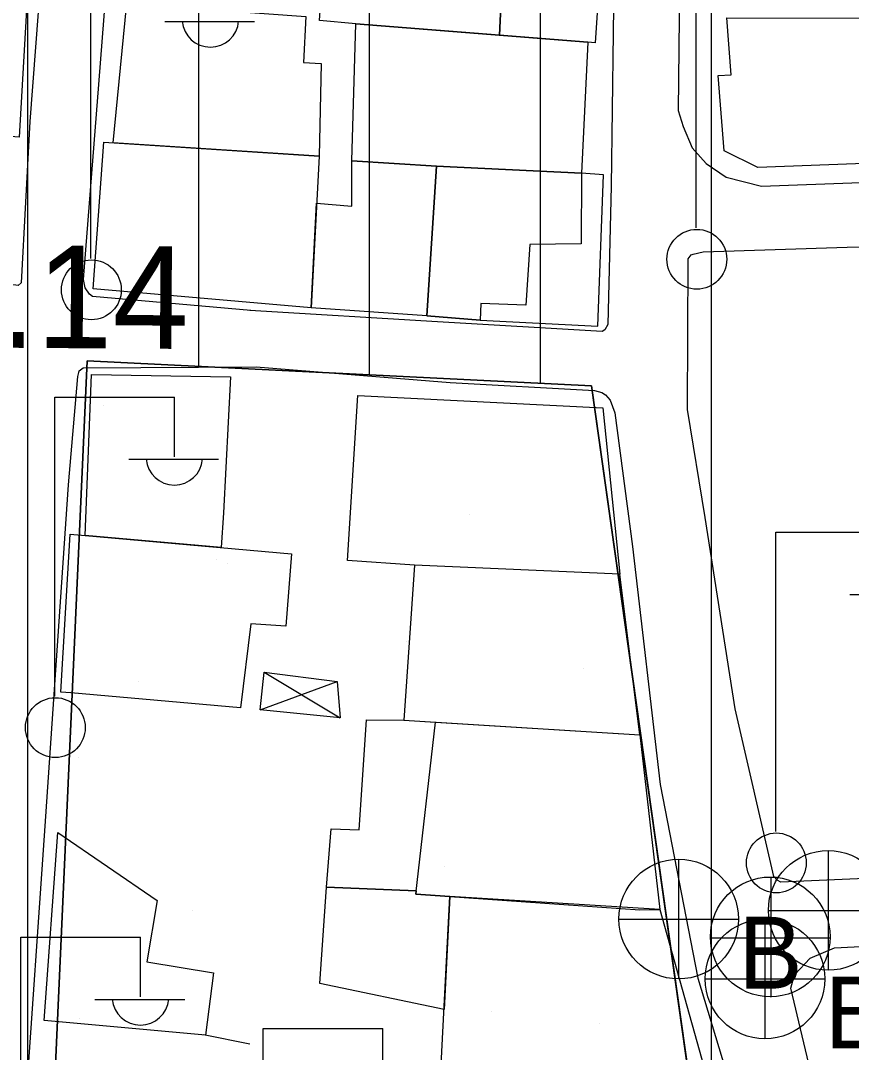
# Model space of a CAD drawing. Extents: x 417997 to 421451, y 4451742 to 4455216.
# Drawn here: x 419705.5 to 419754.1, y 4452544.2 to 4452604.6 of the extents above; entities that cross this region are included whole.
import ezdxf

# ---------------------------------------------------------------- set-up
doc = ezdxf.new("R2010")
doc.units = 0
for name, color, linetype in [('ADA', 7, 'Continuous'), ('B_Mesken', 7, 'Continuous'), ('B_Sundurma', 7, 'Continuous'), ('B_Teras', 7, 'Continuous'), ('Default', 7, 'Continuous'), ('PL_AYA_PARK_DINLENME', 7, 'Continuous'), ('PL_KON_MEV_350', 7, 'Continuous'), ('S_Elektrik_Diregi', 7, 'Continuous'), ('S_Rogar_Kapagi', 7, 'Continuous'), ('S_Rogar_Kapagi_Buski', 7, 'Continuous'), ('Sinir_Duvar_tek_tarafa_ait', 7, 'Continuous'), ('TR_ORTAYOGUNKONUT', 7, 'Continuous'), ('TR_PARKALANI', 7, 'Continuous'), ('Y_Yol_Kotu', 7, 'Continuous'), ('Yol_Sose', 7, 'Continuous')]:
    doc.layers.add(name, color=color, linetype=linetype)

# ---------------------------------------------------------------- blocks, each defined once
blk = doc.blocks.new('POINT_DISPLAY')
at = {"layer": 'Default'}
blk.add_line((0, 0), (0, 0), dxfattribs=at)

msp = doc.modelspace()

# ---------------------------------------------------------------- linework, layer by layer
at = {"layer": 'ADA'}
for p, q in [((419707.455, 4452540.909), (419709.422, 4452584.671)), ((419707.455, 4452540.909), (419709.422, 4452584.671)), ((419709.422, 4452584.671), (419738.924, 4452583.196)), ((419709.422, 4452584.671), (419738.924, 4452583.196)), ((419738.924, 4452583.196), (419744.825, 4452541.401)), ((419738.924, 4452583.196), (419744.825, 4452541.401))]:
    msp.add_line(p, q, dxfattribs=at)
at = {"layer": 'B_Mesken'}
for points in [[(419725.136, 4452604.384), (419723.02, 4452604.57), (419723.711, 4452614.614), (419729.791, 4452613.902), (419733.998, 4452613.408), (419733.54, 4452603.719)], [(419733.54, 4452603.719), (419733.998, 4452613.408), (419738.936, 4452613.018), (419739.793, 4452612.964), (419739.15, 4452603.264), (419738.71, 4452603.311)], [(419755.808, 4452613.02), (419762.653, 4452613.18), (419764.246, 4452596.565), (419748.658, 4452595.965), (419746.701, 4452596.949), (419746.336, 4452601.351), (419747.097, 4452601.395), (419746.849, 4452604.727), (419755.984, 4452604.701)], [(419691.408, 4452598.864), (419691.916, 4452607.049), (419705.904, 4452605.887), (419705.445, 4452597.747)], [(419710.938, 4452597.42), (419711.726, 4452605.396), (419715.187, 4452605.307), (419722.209, 4452604.812), (419722.08, 4452602.108), (419723.121, 4452602.056), (419722.993, 4452596.633)], [(419729.864, 4452596.047), (419724.919, 4452596.356), (419725.136, 4452604.384), (419738.71, 4452603.311), (419738.352, 4452595.65)], [(419709.77, 4452588.87), (419710.401, 4452597.455), (419722.993, 4452596.633), (419722.531, 4452587.768)], [(419729.294, 4452587.299), (419722.531, 4452587.768), (419722.85, 4452593.888), (419724.918, 4452593.721), (419724.919, 4452596.356), (419729.864, 4452596.047)], [(419732.417, 4452587.046), (419739.305, 4452586.691), (419739.636, 4452595.544), (419738.352, 4452595.65), (419729.864, 4452596.047), (419729.294, 4452587.299)], [(419717.404, 4452575.786), (419717.257, 4452573.75), (419709.305, 4452574.453), (419709.676, 4452583.866), (419717.808, 4452583.737)], [(419725.254, 4452582.646), (419739.591, 4452581.914), (419740.584, 4452572.182), (419728.572, 4452572.725), (419724.657, 4452572.985)], [(419708.468, 4452565.241), (419707.881, 4452565.283), (419708.424, 4452574.531), (419721.382, 4452573.385), (419721.055, 4452569.141), (419718.996, 4452569.288), (419718.394, 4452564.379)], [(419728.572, 4452572.725), (419727.956, 4452563.649), (419741.769, 4452562.795), (419740.584, 4452572.182)], [(419728.682, 4452553.676), (419723.432, 4452553.884), (419723.705, 4452557.286), (419725.341, 4452557.237), (419725.759, 4452563.675), (419727.956, 4452563.649), (419729.797, 4452563.535), (419741.769, 4452562.795), (419742.93, 4452552.576), (419730.642, 4452553.345), (419728.66, 4452553.483)], [(419730.303, 4452546.725), (419723.039, 4452548.243), (419723.432, 4452553.884), (419728.682, 4452553.676), (419728.66, 4452553.483), (419730.642, 4452553.345)], [(419741.768, 4452552.558), (419742.93, 4452552.576), (419747.406, 4452536.654), (419730.1, 4452542.755), (419730.642, 4452553.345)]]:
    msp.add_lwpolyline(points, close=True, dxfattribs=at)
at = {"layer": 'B_Sundurma'}
for p, q in [((419719.785, 4452566.456), (419724.228, 4452563.786)), ((419719.555, 4452564.261), (419724.06, 4452565.909))]:
    msp.add_line(p, q, dxfattribs=at)
msp.add_lwpolyline([(419719.555, 4452564.261), (419719.785, 4452566.456), (419724.06, 4452565.909), (419724.228, 4452563.786)], close=True, dxfattribs=at)
at = {"layer": 'B_Teras'}
for points in [[(419729.294, 4452587.299), (419729.864, 4452596.047), (419738.352, 4452595.65), (419738.33, 4452591.504), (419735.317, 4452591.465), (419735.091, 4452587.921), (419732.466, 4452588.029), (419732.417, 4452587.046)], [(419741.769, 4452562.795), (419742.93, 4452552.576), (419730.642, 4452553.345), (419728.66, 4452553.483), (419729.797, 4452563.535)], [(419706.905, 4452546.091), (419707.717, 4452557.085), (419713.521, 4452553.105), (419712.907, 4452549.513), (419716.825, 4452548.876), (419716.345, 4452545.231)]]:
    msp.add_lwpolyline(points, close=True, dxfattribs=at)
at = {"layer": 'PL_AYA_PARK_DINLENME'}
msp.add_lwpolyline([(419738.924, 4452583.196), (419744.825, 4452541.401), (419707.455, 4452540.909), (419709.422, 4452584.671)], close=True, dxfattribs=at)
msp.add_lwpolyline([(419738.924, 4452583.196), (419744.825, 4452541.401), (419707.455, 4452540.909), (419709.422, 4452584.671)], close=True, dxfattribs=at)
at = {"layer": 'PL_KON_MEV_350'}
msp.add_lwpolyline([(419816.019, 4452500.983), (419737, 4452491.84), (419733.027, 4452491.433), (419729.045, 4452491.133), (419725.057, 4452490.939), (419721.064, 4452490.851), (419717.071, 4452490.869), (419713.08, 4452490.994), (419709.093, 4452491.225), (419705.114, 4452491.562), (419667.93, 4452495.209), (419665.168, 4452517.307), (419707.455, 4452540.909), (419744.825, 4452541.401), (419738.924, 4452583.196), (419709.422, 4452584.671), (419707.455, 4452540.909), (419665.168, 4452517.307), (419625.831, 4452515.34), (419623.77, 4452499.541), (419582.687, 4452503.571)], dxfattribs=at)
at = {"layer": 'S_Elektrik_Diregi'}
for p, q in [((419745.06, 4452592.442), (419745.06, 4452609.942)), ((419709.634, 4452590.657), (419709.634, 4452608.157)), ((419713.974, 4452604.517), (419719.224, 4452604.517)), ((419707.525, 4452565.049), (419707.525, 4452582.549)), ((419707.525, 4452582.549), (419714.525, 4452582.549)), ((419714.525, 4452579.049), (419714.525, 4452582.549)), ((419711.865, 4452578.909), (419717.115, 4452578.909)), ((419749.711, 4452557.138), (419749.711, 4452574.638)), ((419749.711, 4452574.638), (419756.711, 4452574.638)), ((419754.051, 4452570.998), (419759.301, 4452570.998)), ((419705.541, 4452533.46), (419705.541, 4452550.96)), ((419705.541, 4452550.96), (419712.541, 4452550.96)), ((419712.541, 4452547.46), (419712.541, 4452550.96)), ((419709.881, 4452547.32), (419715.131, 4452547.32)), ((419719.718, 4452528.113), (419719.717, 4452545.613)), ((419719.717, 4452545.613), (419726.718, 4452545.613)), ((419726.718, 4452542.113), (419726.718, 4452545.613))]:
    msp.add_line(p, q, dxfattribs=at)
for centre in [(419745.096, 4452590.606), (419709.67, 4452588.822), (419707.561, 4452563.214), (419749.747, 4452555.302)]:
    msp.add_circle(centre, 1.75, dxfattribs=at)
for centre in [(419716.635, 4452604.67), (419714.526, 4452579.062), (419712.542, 4452547.473)]:
    msp.add_arc(centre, 1.658, 184.83843, 355.14641, dxfattribs=at)
at = {"layer": 'S_Rogar_Kapagi'}
for p, q in [((419749.445, 4452547.449), (419749.445, 4452554.449)), ((419745.875, 4452550.914), (419752.875, 4452550.914))]:
    msp.add_line(p, q, dxfattribs=at)
msp.add_circle((419749.392, 4452550.977), 3.5, dxfattribs=at)
at = {"layer": 'S_Rogar_Kapagi_Buski'}
for p, q in [((419752.782, 4452556.025), (419752.782, 4452549.025)), ((419744.032, 4452555.515), (419744.032, 4452548.515)), ((419749.282, 4452552.525), (419756.282, 4452552.525)), ((419740.532, 4452552.015), (419747.532, 4452552.015)), ((419749.082, 4452552.015), (419749.082, 4452545.015)), ((419745.582, 4452548.515), (419752.582, 4452548.515))]:
    msp.add_line(p, q, dxfattribs=at)
for centre in [(419752.782, 4452552.525), (419744.032, 4452552.015), (419749.082, 4452548.515)]:
    msp.add_circle(centre, 3.5, dxfattribs=at)
at = {"layer": 'Sinir_Duvar_tek_tarafa_ait'}
msp.add_lwpolyline([(419718.939, 4452544.697), (419716.228, 4452545.242)], dxfattribs=at)
at = {"layer": 'TR_ORTAYOGUNKONUT'}
for p, q in [((419745.951, 4452492.875), (419745.951, 4452648.087)), ((419745.951, 4452492.875), (419745.951, 4452648.087)), ((419735.951, 4452583.345), (419735.951, 4452645.493)), ((419735.951, 4452583.345), (419735.951, 4452645.493)), ((419725.951, 4452583.845), (419725.951, 4452642.899)), ((419725.951, 4452583.845), (419725.951, 4452642.899)), ((419715.951, 4452584.345), (419715.951, 4452640.305)), ((419715.951, 4452584.345), (419715.951, 4452640.305)), ((419705.951, 4452491.491), (419705.951, 4452637.711)), ((419705.951, 4452491.491), (419705.951, 4452637.711))]:
    msp.add_line(p, q, dxfattribs=at)
at = {"layer": 'Yol_Sose'}
for points in [[(419692.481, 4452655.655), (419692.72, 4452656.346), (419693.218, 4452656.668), (419706.643, 4452655.051), (419709.694, 4452654.512), (419710.002, 4452654.022), (419710.016, 4452652.897), (419709.009, 4452642.33), (419707.72, 4452620.414), (419706.071, 4452598.67), (419705.561, 4452589.236), (419705.39, 4452589.081), (419705.258, 4452589.083), (419688.558, 4452590.846), (419688.256, 4452591.532), (419688.8, 4452600.219), (419689.17, 4452618.798), (419690.101, 4452641.63), (419690.761, 4452645.022)], [(419719.003, 4452587.601), (419709.742, 4452588.431), (419709.569, 4452588.567), (419709.305, 4452588.943), (419709.214, 4452589.416), (419710.1, 4452600.829), (419711.66, 4452620.827), (419713.55, 4452646.751), (419713.881, 4452652.166), (419714.276, 4452652.495), (419714.807, 4452652.567), (419743.028, 4452649.28), (419743.3, 4452648.998), (419743.366, 4452648.396), (419742.419, 4452637.95), (419740.317, 4452612.843), (419740.077, 4452594.873), (419739.883, 4452586.794), (419739.722, 4452586.484), (419739.562, 4452586.387), (419729.917, 4452586.945)], [(419765.318, 4452631.365), (419748.046, 4452631.838), (419747.841, 4452631.823), (419747.681, 4452631.74), (419747.399, 4452631.563), (419747.155, 4452631.318), (419746.852, 4452630.757), (419744.163, 4452613.82), (419744.01, 4452599.303), (419744.292, 4452598.365), (419744.831, 4452597.131), (419745.632, 4452596.206), (419746.821, 4452595.399), (419748.885, 4452594.886), (419759.97, 4452595.294)], [(419829.472, 4452584.824), (419826.698, 4452565.291), (419825.85, 4452558.862), (419825.7, 4452558.501), (419825.499, 4452558.341), (419825.154, 4452558.213), (419816.036, 4452557.607), (419788.895, 4452556.232), (419763.46, 4452554.757), (419750.014, 4452554.177), (419749.79, 4452554.302), (419749.593, 4452554.506), (419747.338, 4452564.311), (419745.583, 4452575.501), (419744.543, 4452581.826), (419744.593, 4452590.636), (419744.769, 4452590.856), (419744.883, 4452590.914), (419745.46, 4452591.032), (419753.899, 4452591.316), (419775.994, 4452591.756)], [(419729.917, 4452586.945), (419718.937, 4452587.607)], [(419698.521, 4452420.049), (419699.627, 4452436.866), (419700.872, 4452451.862), (419701.746, 4452469.808), (419702.712, 4452489.739), (419703.618, 4452506.403), (419704.574, 4452521.13), (419705.789, 4452540.585), (419706.985, 4452557.737), (419708.34, 4452577.414), (419708.883, 4452583.751), (419708.936, 4452583.987), (419708.965, 4452584.087), (419709.195, 4452584.252), (419719.319, 4452584.32), (419730.666, 4452583.405)], [(419730.666, 4452583.405), (419739.114, 4452582.925), (419739.528, 4452582.815), (419739.75, 4452582.668), (419740.033, 4452582.357), (419740.293, 4452581.625), (419741.339, 4452573.807), (419742.959, 4452559.89), (419745.157, 4452548.564), (419751.43, 4452527.847), (419751.435, 4452527.512), (419751.299, 4452527.137), (419751.118, 4452526.946), (419750.819, 4452526.83), (419745.646, 4452526.818), (419721.468, 4452526.742), (419721.46, 4452525.514), (419738.068, 4452525.52), (419751.873, 4452524.892), (419752.15, 4452524.8), (419752.564, 4452524.384), (419758.02, 4452511.928)], [(419755.325, 4452532.858), (419751.919, 4452542.396), (419750.587, 4452547.986), (419750.811, 4452548.763), (419751.725, 4452549.73), (419753.159, 4452550.34), (419774.685, 4452551.42)]]:
    msp.add_lwpolyline(points, dxfattribs=at)

# ---------------------------------------------------------------- block references
at = {"layer": 'TR_PARKALANI', "xscale": 0.1, "yscale": 0.10000000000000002}
for p in [(419730.7, 4452583.001), (419730.7, 4452583.001), (419710.357, 4452582.038), (419710.357, 4452582.038), (419731.79, 4452575.663), (419731.79, 4452575.663), (419717.017, 4452573.058), (419717.017, 4452573.058), (419717.655, 4452572.784), (419717.655, 4452572.784), (419728.095, 4452568.229), (419728.095, 4452568.229), (419738.45, 4452566.683), (419738.45, 4452566.683), (419712.455, 4452565.909), (419712.455, 4452565.909), (419723.678, 4452564.078), (419723.678, 4452564.078), (419708.906, 4452561.474), (419708.906, 4452561.474), (419741.999, 4452560.7), (419741.999, 4452560.7), (419730.338, 4452555.099), (419730.338, 4452555.099), (419715.566, 4452552.494), (419715.566, 4452552.494), (419733.108, 4452546.588), (419733.108, 4452546.588), (419708.982, 4452546.213), (419708.982, 4452546.213), (419739.394, 4452545.928), (419739.394, 4452545.928)]:
    msp.add_blockref('POINT_DISPLAY', p, dxfattribs=at)

# ---------------------------------------------------------------- texts
at = {"layer": 'S_Rogar_Kapagi_Buski'}
for p in [(419747.532, 4452547.951), (419752.582, 4452544.451)]:
    msp.add_text('B', height=4.2, dxfattribs=at).set_placement(p)
at = {"layer": 'Y_Yol_Kotu'}
msp.add_text('123.14 ', height=6, rotation=359.61735, dxfattribs=at).set_placement((419690.818, 4452585.524))

doc.saveas('drawing.dxf')
